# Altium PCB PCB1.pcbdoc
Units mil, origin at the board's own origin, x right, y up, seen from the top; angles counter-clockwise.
Board outline 7575 x 3530 mil, 2 copper layers (Top Layer, Bottom Layer); 5 components, 5 nets, 21 pads, 0 vias.
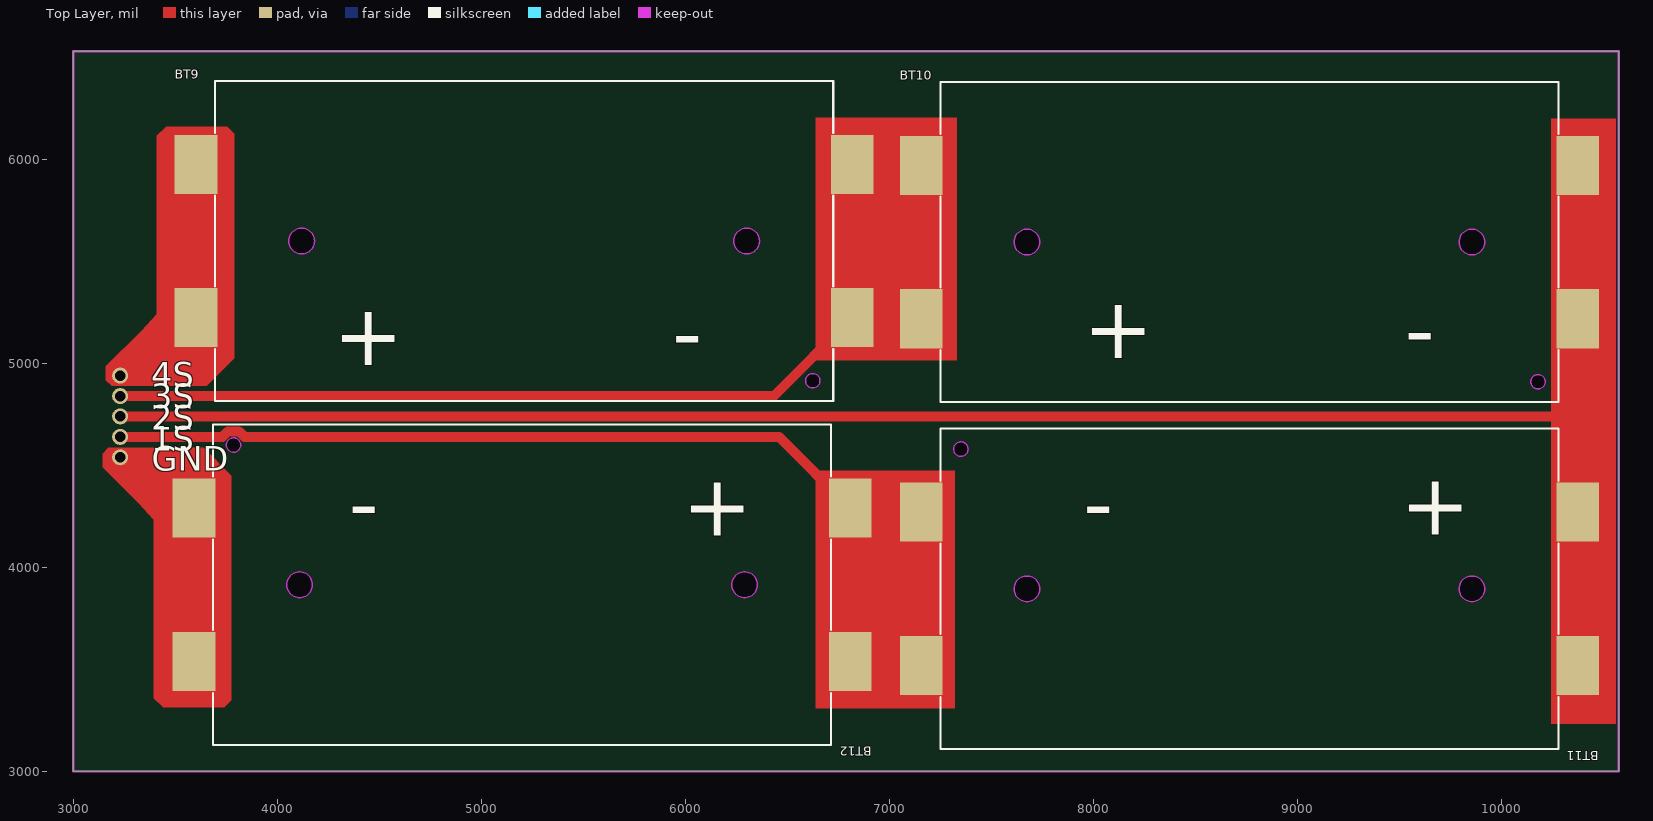
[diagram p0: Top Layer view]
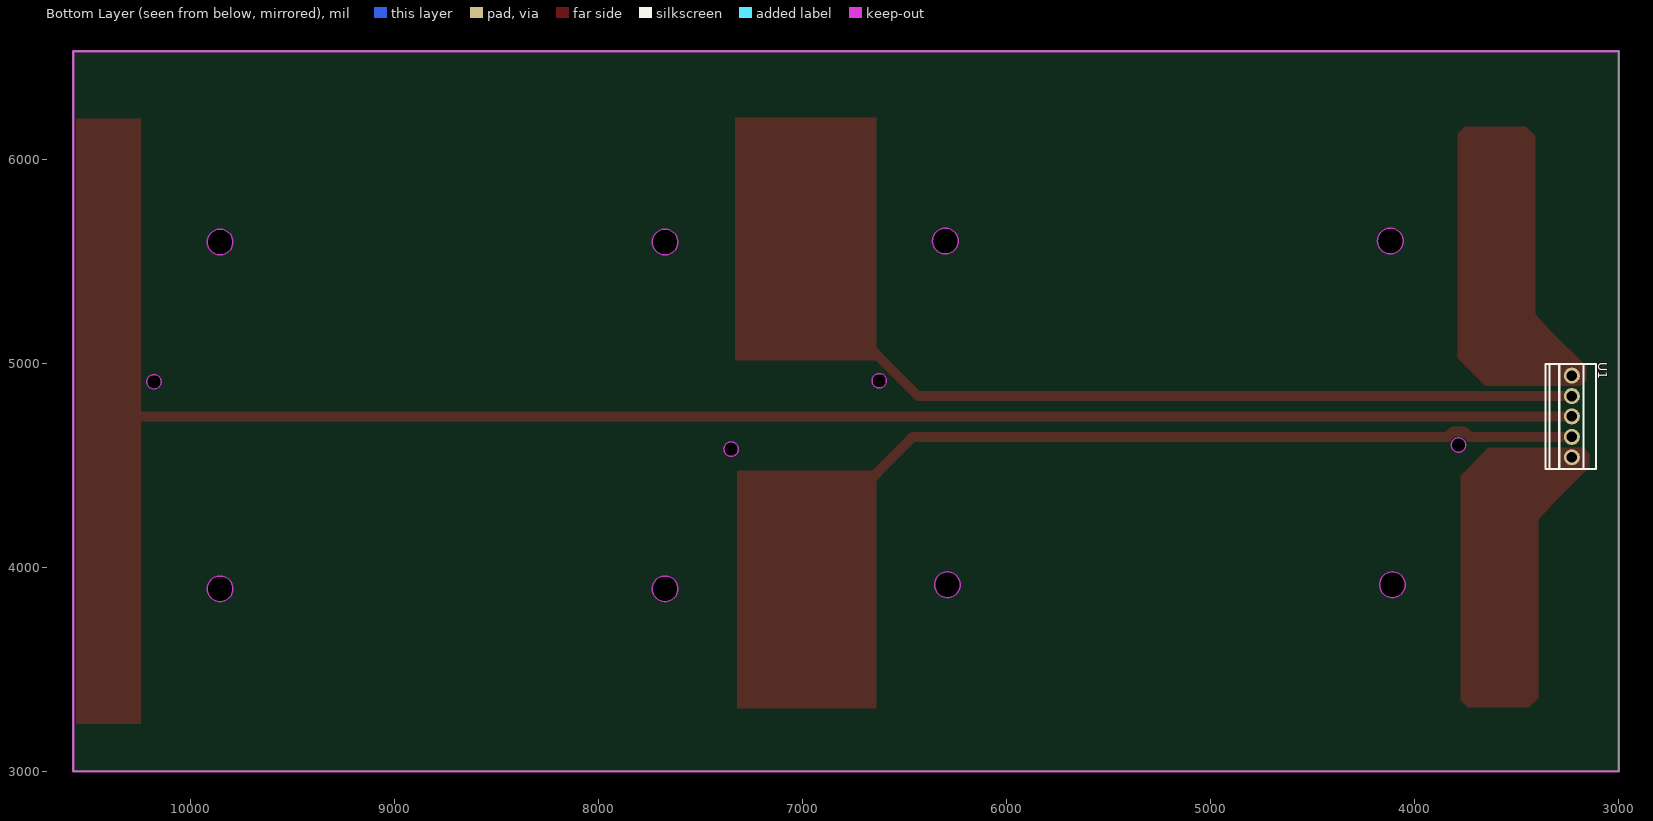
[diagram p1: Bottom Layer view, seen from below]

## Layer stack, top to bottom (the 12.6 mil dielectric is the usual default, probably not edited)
Top Layer: signal copper (thickness not stored)
Dielectric: dielectric 12.6, FR-4, Dk 4.8
Bottom Layer: signal copper (thickness not stored)

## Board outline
3000,6530 10575,6530 10575,3000 3000,3000

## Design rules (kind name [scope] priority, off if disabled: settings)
BoardOutlineClearance copperThickness1oz [All] p0: genericclearance=10 ignorepadtopadclearanceinfootprint=FALSE except(0: Arc-SplitContinuation Track-SplitContinuation SMDPad-SplitContinuation THPad-SplitContinuation Via-SplitContinuation Fill-SplitContinuation Poly-SplitContinuation Region-SplitContinuation Text-SplitContinuation; 6: Track-CutoutEdge SMDPad-CutoutEdge THPad-CutoutEdge Via-CutoutEdge Region-CutoutEdge; 11.8: Track-OutlineEdge SMDPad-OutlineEdge THPad-OutlineEdge Via-OutlineEdge Fill-OutlineEdge Region-OutlineEdge Poly-OutlineEdge Text-OutlineEdge Fill-CutoutEdge)
BoardOutlineClearance copperThickness2oz [All] p0: genericclearance=10 ignorepadtopadclearanceinfootprint=FALSE except(0: Arc-SplitContinuation Track-SplitContinuation SMDPad-SplitContinuation THPad-SplitContinuation Via-SplitContinuation Fill-SplitContinuation Poly-SplitContinuation Region-SplitContinuation Text-SplitContinuation; 6: Track-CutoutEdge SMDPad-CutoutEdge THPad-CutoutEdge Via-CutoutEdge Region-CutoutEdge; 11.8: Track-OutlineEdge SMDPad-OutlineEdge THPad-OutlineEdge Via-OutlineEdge Fill-OutlineEdge Region-OutlineEdge Poly-OutlineEdge Text-OutlineEdge Fill-CutoutEdge)
Clearance copperThickness1oz [(InNet('$1N303') OR InNet('$1N294') OR InNet('$1N285') OR InNet('$1N276') OR InNet('GND'))] p1: gap=7 ignorepadtopadclearanceinfootprint=FALSE except(4: Track-Track; 6: Track-SMDPad SMDPad-SMDPad Track-THPad SMDPad-THPad THPad-THPad Track-Via SMDPad-Via THPad-Via Via-Via SMDPad-Fill THPad-Fill Via-Fill Fill-Fill Track-Region SMDPad-Region THPad-Region Via-Region Region-Region Track-Poly SMDPad-Poly THPad-Poly Via-Poly Fill-Poly Region-Poly Poly-Poly Track-Text SMDPad-Text THPad-Text Via-Text Fill-Text Region-Text Poly-Text Text-Text; 6.9: Track-Hole SMDPad-Hole THPad-Hole Via-Hole Fill-Hole Region-Hole Poly-Hole Text-Hole Sheet-Hole; 11.8: Track-Fill Fill-Region Track-Sheet SMDPad-Sheet THPad-Sheet Via-Sheet Fill-Sheet Region-Sheet Poly-Sheet Text-Sheet)
Clearance copperThickness2oz [All] p1: gap=7 ignorepadtopadclearanceinfootprint=FALSE except(6: Track-SMDPad SMDPad-SMDPad Track-THPad SMDPad-THPad THPad-THPad Track-Via SMDPad-Via THPad-Via Via-Via SMDPad-Fill THPad-Fill Via-Fill Fill-Fill Track-Region SMDPad-Region THPad-Region Via-Region Region-Region Track-Poly SMDPad-Poly THPad-Poly Via-Poly Fill-Poly Region-Poly Poly-Poly Track-Text SMDPad-Text THPad-Text Via-Text Fill-Text Region-Text Poly-Text Text-Text; 6.9: Track-Hole SMDPad-Hole THPad-Hole Via-Hole Fill-Hole Region-Hole Poly-Hole Text-Hole Sheet-Hole; 8: Track-Track; 11.8: Track-Fill Fill-Region Track-Sheet SMDPad-Sheet THPad-Sheet Via-Sheet Fill-Sheet Region-Sheet Poly-Sheet Text-Sheet)
DiffPairsRouting differentialPair [All] p1: maxuncoupledlength=10 minlimit=6 maxlimit=6 mostfreqgap=6 toplayer_minwidth=5 toplayer_prefwidth=10 toplayer_maxwidth=100 bottomlayer_minwidth=5 bottomlayer_prefwidth=10 bottomlayer_maxwidth=100
PasteMaskExpansion pasteMaskExpansion [All] p1: expansion=0
PlaneConnect innerPlane [All] p1: planeconnectstyle=Relief reliefexpansion=20 reliefentries=4 reliefconductorwidth=10 reliefairgap=10
PolygonConnect copperRegion [All] p1: connectstyle=Relief reliefentries=4 reliefconductorwidth=10 polygonreliefangle="90 Angle" airgapwidth=10
RoutingVias viaSize [All] p1: viastyle="Through Hole" holewidth=12.0078 minholewidth=11.811 maxholewidth=248.0314 width=24.0158 minwidth=19.685 maxwidth=393.7008
SolderMaskExpansion solderMaskExpansion [All] p1: useseparateexpansions=TRUE expansion=2 expansionbottom=2
Width copperThickness1oz [All] p1: maxlimit=100 minlimit=5 preferedwidth=10
Width copperThickness2oz [All] p1: maxlimit=100 minlimit=8 preferedwidth=10

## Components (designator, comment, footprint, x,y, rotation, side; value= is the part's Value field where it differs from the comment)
BT9 "BH-18650-B1BA007" BAT-SMD_BH-18650-B1BA007 5210,5600 r0 top
BT10 "BH-18650-B1BA007" BAT-SMD_BH-18650-B1BA007 8765,5595 r0 top
BT11 "BH-18650-B1BA007" BAT-SMD_BH-18650-B1BA007 8765,3895 r180 top
BT12 "BH-18650-B1BA007" BAT-SMD_BH-18650-B1BA007 5200,3915 r180 top
U1 "KF128-2.54-5P" CONN-TH_5P-P2.54_KF128-2.54-5P 3230,4740 r270 bottom

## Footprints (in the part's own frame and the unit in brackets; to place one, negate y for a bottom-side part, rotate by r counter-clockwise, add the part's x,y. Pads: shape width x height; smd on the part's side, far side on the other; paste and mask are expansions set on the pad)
BAT-SMD_BH-18650-B1BA007 [mm]
  rect 5.32x7.35 smd: 1(-40.855,9.55) 2(40.855,9.55) 3(-40.855,-9.55) 4(40.855,-9.55)
  Board Outline Layer circle w0.005: c-27.7,0 r1.6
  Board Outline Layer circle w0.005: c27.7,0 r1.6
  Board Outline Layer circle w0.005: c35.93,-17.4 r0.9
  Board Outline Layer region: -26.1,0 -26.258,-0.694 -26.702,-1.251 -27.344,-1.56 -28.056,-1.56 -28.698,-1.251 -29.142,-0.694 -29.3,0 -29.3,0 -29.142,0.694 -28.698,1.251 -28.056,1.56 -27.344,1.56 -26.702,1.251 -26.258,0.694 -26.1,0
  Board Outline Layer region: 29.3,0 29.142,-0.694 28.698,-1.251 28.056,-1.56 27.344,-1.56 26.702,-1.251 26.258,-0.694 26.1,0 26.1,0 26.258,0.694 26.702,1.251 27.344,1.56 28.056,1.56 28.698,1.251 29.142,0.694 29.3,0
  Board Outline Layer region: 36.83,-17.4 36.741,-17.79 36.491,-18.104 36.13,-18.277 35.73,-18.277 35.369,-18.104 35.119,-17.79 35.03,-17.4 35.03,-17.4 35.119,-17.009 35.369,-16.696 35.73,-16.522 36.13,-16.522 36.491,-16.696 36.741,-17.009 36.83,-17.4
  Multi-Layer board cut-out: -26.1,0 -26.258,-0.694 -26.702,-1.251 -27.344,-1.56 -28.056,-1.56 -28.698,-1.251 -29.142,-0.694 -29.3,0 -29.3,0 -29.142,0.694 -28.698,1.251 -28.056,1.56 -27.344,1.56 -26.702,1.251 -26.258,0.694 -26.1,0
  Multi-Layer board cut-out: 29.3,0 29.142,-0.694 28.698,-1.251 28.056,-1.56 27.344,-1.56 26.702,-1.251 26.258,-0.694 26.1,0 26.1,0 26.258,0.694 26.702,1.251 27.344,1.56 28.056,1.56 28.698,1.251 29.142,0.694 29.3,0
  Multi-Layer board cut-out: 36.83,-17.4 36.741,-17.79 36.491,-18.104 36.13,-18.277 35.73,-18.277 35.369,-18.104 35.119,-17.79 35.03,-17.4 35.03,-17.4 35.119,-17.009 35.369,-16.696 35.73,-16.522 36.13,-16.522 36.491,-16.696 36.741,-17.009 36.83,-17.4
  silkscreen extent -38.48,-19.94 38.48,19.94
CONN-TH_5P-P2.54_KF128-2.54-5P [mm]
  round 2 hole 1.3: 1(-5.08,0) 2(-2.54,0) 3(0,0) 4(2.54,0) 5(5.08,0)
  silkscreen extent -6.55,-3.3 6.55,3

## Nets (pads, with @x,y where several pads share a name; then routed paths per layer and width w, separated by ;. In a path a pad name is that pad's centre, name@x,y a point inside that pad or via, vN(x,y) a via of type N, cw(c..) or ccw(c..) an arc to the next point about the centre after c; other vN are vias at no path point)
$1N276: BT11.2 BT11.4 BT12.1 BT12.3 U1.4 | length 3744.9
  Top Layer w50: U1.4 3731.47,4640 3757.92,4666.45 3812.94,4666.45 3839.39,4640 6459.44,4640 BT12.3
$1N285: BT10.2 BT10.4 BT11.1 BT11.3 U1.3 | length 7146.2
  Top Layer w50: U1.3 10355,4740 10370,4755
$1N294: BT9.2 BT9.4 BT10.1 BT10.3 U1.2 | length 3747.5
  Top Layer w50: U1.2 6434.44,4840 BT9.4
$1N303: BT9.1 BT9.3 U1.1
GND: BT12.2 BT12.4 U1.5

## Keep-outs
Board Outline Layer:
  the board outline again, w10

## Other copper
Top Layer:
  region net $1N294: 6640,6205 7330,6205 7330,5015 6640,5015
  region net $1N276: 6640,4475 7320,4475 7320,3310 6640,3310
  region net $1N285: 10245,6200 10560,6200 10560,3235 10245,3235
  region net GND: 3395,4234.1 3395,3360 3440,3315 3740,3315 3775,3350 3775,4450 3639.34,4585.66 3172.6,4585.66 3145,4558.06 3145,4490 3320,4315
  region net $1N303: 3410,5241.23 3410,6115.33 3455,6160.33 3755,6160.33 3790,6125.33 3790,5025.33 3654.34,4889.67 3187.6,4889.67 3160,4917.27 3160,4985.33 3335,5160.33

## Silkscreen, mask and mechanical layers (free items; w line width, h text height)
Top Silkscreen Layer:
  text "+" at 7950,5025 h300
  text "-" at 9525,5020 h300
  text "-" at 5935,5005 h300
  text "+" at 4275,4990 h300
  text "4S" at 3381.48,4885.06 h120
  text "3S" at 3381.48,4779.71 h120
  text "2S" at 3381.48,4674.36 h120
  text "1S" at 3381.48,4570.77 h120
  text "GND" at 3385,4475 h120
  text "-" at 4350,4170 h300
  text "-" at 7950,4170 h300
  text "+" at 9505,4160 h300
  text "+" at 5985,4155 h300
